(* Logix 5000 project; controller MVI94ADMSerialIn 1756-L63 rev 11.1; software revision 11.13 *)
// Example Logic for the MVI56-ADM module.

TASK MainTask (task) : MainProgram

MODULES
   Local : 1756-L63 (rev 11.1)
      Bridge : 1756-CNB (rev 1.1)
         MVI94ADM : 1794-ACN15 (rev 4.1, Output RPI 5 ms)
            ADM : vendor 1 type 107 code 1 (rev 1.1, Output RPI 5 ms)
END_MODULES

TYPE ADMModuleDef :
STRUCT
   ReadData : INT[600];
   WriteData : INT[600];
END_STRUCT
END_TYPE

VAR_GLOBAL   (* controller tags *)
   ADM : ADMModuleDef;
   ColdBoot : BOOL;
   MJFAULTS : DINT[12] := ([0] := -491726278, [1] := 191080, [3] := -495837906, [4] := 191080);
   SendDataPort1 : BOOL;
   SerialCount : INT := 8;
   WarmBoot : BOOL;
END_VAR

PROGRAM MainProgram   (* routine attr 65 MainRoutine *)

ROUTINE MainRoutine   (* ladder *)
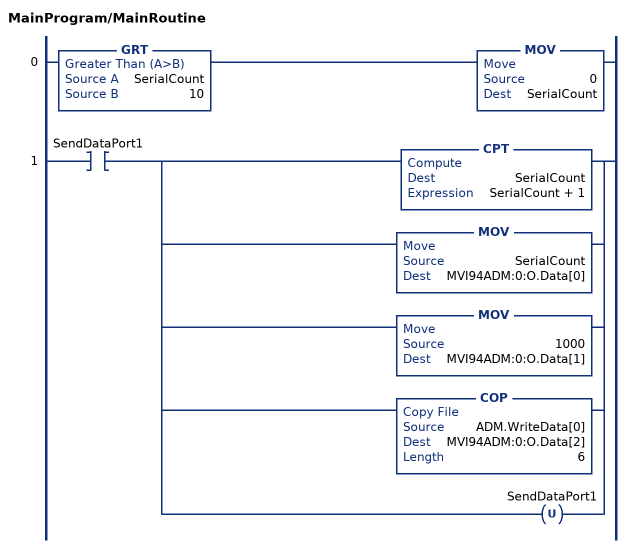
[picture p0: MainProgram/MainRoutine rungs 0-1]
   0: GRT(SerialCount,10)MOV(0,SerialCount);
   1: XIC(SendDataPort1)[CPT(SerialCount,SerialCount + 1) ,MOV(SerialCount,MVI94ADM:0:O.Data[0]) ,MOV(1000,MVI94ADM:0:O.Data[1]) ,COP(ADM.WriteData[0],MVI94ADM:0:O.Data[2],6) ,OTU(SendDataPort1) ];
END_ROUTINE
END_PROGRAM

PROGRAM StartUp   (* routine attr 65 PowerUp *)

ROUTINE PowerUp   (* ladder *)
END_ROUTINE
END_PROGRAM
